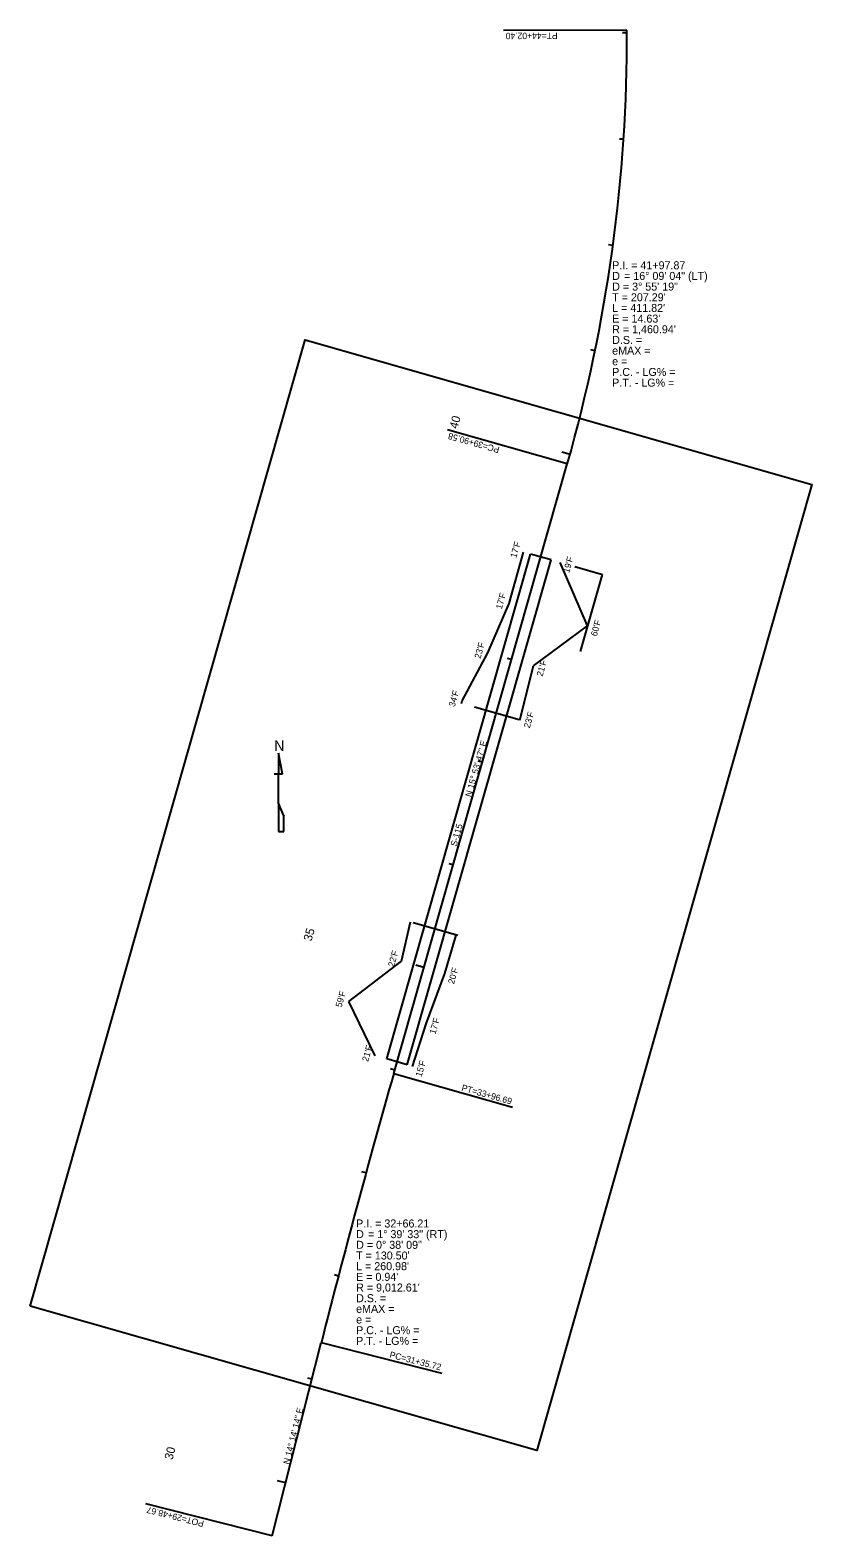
# Model space of a CAD drawing. Extents: x 1619269 to 1623088, y 1189107 to 1192385.
# Drawn here: x 1619269 to 1620002, y 1190974 to 1192385 of the extents above; entities that cross this region are included whole.
import ezdxf

# ---------------------------------------------------------------- set-up
doc = ezdxf.new("R2010")
doc.units = 0
for name, color, linetype in [('GN_Clip', 7, 'Continuous'), ('RD_EX_Misc', 7, 'Continuous'), ('RD_HC_Cl', 7, 'Continuous'), ('RD_HC_Data', 7, 'Continuous'), ('RD_HC_Data_Tic', 7, 'Continuous'), ('RD_HC_TX_Sta50', 7, 'Continuous'), ('RD_PD_Bridge', 7, 'Continuous'), ('RD_PD_CstnLmt', 7, 'Continuous'), ('RD_PD_CstnLmt_TX', 7, 'Continuous'), ('RD_PD_Final_TrvlWay', 7, 'Continuous'), ('RD_PD_RW', 7, 'Continuous'), ('RD_TX_RoadID', 7, 'Continuous')]:
    doc.layers.add(name, color=color, linetype=linetype)

msp = doc.modelspace()

# ---------------------------------------------------------------- linework, layer by layer
at = {"layer": 'GN_Clip'}
msp.add_lwpolyline([(1619269.5, 1191189.2), (1619527.3, 1192094.7), (1620002.2, 1191959.4), (1619744.3, 1191054)], close=True, dxfattribs=at)
at = {"layer": 'RD_EX_Misc'}
for p, q in [((1619506.1, 1191688), (1619502.2, 1191707.6)), ((1619502.2, 1191707.6), (1619502.2, 1191707.6)), ((1619502.2, 1191707.6), (1619502.2, 1191688)), ((1619498.3, 1191688), (1619502.2, 1191688)), ((1619502.2, 1191660.8), (1619502.2, 1191688)), ((1619502.2, 1191688), (1619506.1, 1191688)), ((1619506.1, 1191688), (1619506.1, 1191688.3)), ((1619507.1, 1191648.8), (1619502.2, 1191660.8)), ((1619502.2, 1191660.8), (1619502.2, 1191634.1)), ((1619507.1, 1191634.1), (1619507.1, 1191649)), ((1619507.1, 1191649), (1619507.1, 1191648.8)), ((1619502.2, 1191634.1), (1619507.1, 1191634.1))]:
    msp.add_line(p, q, dxfattribs=at)
at = {"layer": 'RD_HC_Cl'}
for p, q in [((1619610.3, 1191407.3), (1619772.9, 1191978.5)), ((1619496.4, 1190974), (1619542.4, 1191155.3))]:
    msp.add_line(p, q, dxfattribs=at)
for centre, radius, start, end in [((1618367.9, 1192378.6), 1460.9, 344.1036, 0.2547), ((1628278.2, 1188938.7), 9012.6, 164.10357, 165.76267)]:
    msp.add_arc(centre, radius, start, end, dxfattribs=at)
at = {"layer": 'RD_HC_Data'}
for p, q in [((1619828.8, 1192385.1), (1619713.1, 1192384.6)), ((1619772.9, 1191978.5), (1619660.7, 1192010.4)), ((1619610.3, 1191407.3), (1619721.5, 1191375.6)), ((1619542.4, 1191155.3), (1619655.4, 1191126.6)), ((1619496.4, 1190974), (1619377.9, 1191004.1))]:
    msp.add_line(p, q, dxfattribs=at)
at = {"layer": 'RD_HC_Data_Tic'}
for p, q in [((1619828.8, 1192382.7), (1619824.8, 1192382.7)), ((1619825.6, 1192282.8), (1619821.7, 1192283)), ((1619815.7, 1192183.3), (1619811.7, 1192183.8)), ((1619798.9, 1192084.7), (1619795, 1192085.5)), ((1619775.5, 1191987.5), (1619767.8, 1191989.7)), ((1619748.1, 1191891.3), (1619744.3, 1191892.4)), ((1619720.7, 1191795.2), (1619716.9, 1191796.3)), ((1619693.3, 1191699), (1619689.5, 1191700.1)), ((1619665.9, 1191602.8), (1619662.1, 1191603.9)), ((1619638.6, 1191506.6), (1619630.9, 1191508.8)), ((1619611.2, 1191410.5), (1619607.3, 1191411.6)), ((1619584.3, 1191314.1), (1619580.4, 1191315.2)), ((1619558.5, 1191217.5), (1619554.6, 1191218.6)), ((1619533.6, 1191120.7), (1619529.8, 1191121.7)), ((1619509, 1191023.7), (1619501.3, 1191025.7))]:
    msp.add_line(p, q, dxfattribs=at)
at = {"layer": 'RD_PD_Bridge'}
for p, q in [((1619727.9, 1191738.6), (1619686.1, 1191750.5)), ((1619670.4, 1191536.6), (1619628.6, 1191548.5))]:
    msp.add_line(p, q, dxfattribs=at)
at = {"layer": 'RD_PD_CstnLmt'}
for p, q in [((1619718.4, 1191847.8), (1619732, 1191895.9)), ((1619792, 1191826.9), (1619766.1, 1191886.2)), ((1619698.4, 1191801.5), (1619718.4, 1191847.8)), ((1619741.2, 1191789.3), (1619792, 1191826.9)), ((1619674.3, 1191756.4), (1619698.4, 1191801.5)), ((1619729.2, 1191740.8), (1619741.2, 1191789.3)), ((1619673.7, 1191754), (1619674.3, 1191756.4)), ((1619728.5, 1191738.4), (1619729.2, 1191740.8)), ((1619617.4, 1191512.7), (1619625.9, 1191549.3)), ((1619658.2, 1191501), (1619668.9, 1191537)), ((1619568.2, 1191474.7), (1619617.4, 1191512.7)), ((1619640.8, 1191454), (1619658.2, 1191501)), ((1619593, 1191423.9), (1619568.2, 1191474.7)), ((1619627.8, 1191414), (1619640.8, 1191454))]:
    msp.add_line(p, q, dxfattribs=at)
at = {"layer": 'RD_PD_Final_TrvlWay'}
for p, q in [((1619603.7, 1191420.9), (1619738.5, 1191894.1)), ((1619623, 1191415.4), (1619757.7, 1191888.6)), ((1619757.7, 1191888.6), (1619738.5, 1191894.1)), ((1619623, 1191415.4), (1619603.7, 1191420.9))]:
    msp.add_line(p, q, dxfattribs=at)
at = {"layer": 'RD_PD_RW'}
for p in [(1619779.9, 1191882.3), (1619785.3, 1191802.8)]:
    msp.add_line(p, (1619805.8, 1191874.9), dxfattribs=at)

# ---------------------------------------------------------------- texts
at = {"layer": 'RD_EX_Misc'}
msp.add_text('N', height=10, dxfattribs=at).set_placement((1619498.2, 1191709.5))
at = {"layer": 'RD_HC_Data'}
for s, rotation, p in [('PT=44+02.40', 180.2547, (1619763.8, 1192382.8)), ('PC=39+90.58', 164.1036, (1619709.9, 1191994.3)), ('N 15%%d 53\' 47" E', 74.1036, (1619682.9, 1191666)), ('PT=33+96.69', 344.1036, (1619673.3, 1191391.4)), ('PC=31+35.72', 345.7627, (1619605.9, 1191141.2)), ('N 14%%d 14\' 14" E', 75.7627, (1619512.3, 1191040.5)), ('POT=29+48.67', 165.7627, (1619432.9, 1190988))]:
    msp.add_text(s, height=6, rotation=rotation, dxfattribs=at).set_placement(p)
for s, p in [('P.I. = 41+97.87', (1619815, 1192161)), ('D', (1619815, 1192151)), ('    = 16%%d 09\' 04" (LT)', (1619815, 1192151)), ('D = 3%%d 55\' 19"', (1619815, 1192141)), ("T = 207.29'", (1619815, 1192131)), ("L = 411.82'", (1619815, 1192121)), ("E = 14.63'", (1619815, 1192111)), ("R = 1,460.94'", (1619815, 1192101)), ('D.S. = ', (1619815, 1192091)), ('eMAX = ', (1619815, 1192081)), ('e = ', (1619815, 1192071)), ('P.C. - LG% = ', (1619815, 1192061)), ('P.T. - LG% = ', (1619815, 1192051)), ('P.I. = 32+66.21', (1619575, 1191263)), ('D', (1619575, 1191253)), ('    = 1%%d 39\' 33" (RT)', (1619575, 1191253)), ("T = 130.50'", (1619575, 1191233)), ('D = 0%%d 38\' 09"', (1619575, 1191243)), ("L = 260.98'", (1619575, 1191223)), ("E = 0.94'", (1619575, 1191213)), ("R = 9,012.61'", (1619575, 1191203)), ('D.S. = ', (1619575, 1191193)), ('eMAX = ', (1619575, 1191183)), ('e = ', (1619575, 1191173)), ('P.C. - LG% = ', (1619575, 1191163)), ('P.T. - LG% = ', (1619575, 1191153))]:
    msp.add_text(s, height=7.5, dxfattribs=at).set_placement(p)
at = {"layer": 'RD_HC_TX_Sta50'}
for s, rotation, p in [('40', 74.473, (1619669.9, 1192010.9)), ('35', 74.1036, (1619533.1, 1191530.7)), ('30', 75.7627, (1619402.9, 1191044.7))]:
    msp.add_text(s, height=8, rotation=rotation, dxfattribs=at).set_placement(p)
at = {"layer": 'RD_PD_CstnLmt_TX'}
for s, p in [("17'F", (1619725.1, 1191890)), ("19'F", (1619774.6, 1191875.9)), ("17'F", (1619711.5, 1191841.9)), ("60'F", (1619800.5, 1191816.6)), ("23'F", (1619691.5, 1191795.6)), ("21'F", (1619749.7, 1191779)), ("34'F", (1619667.4, 1191750.5)), ("23'F", (1619737.7, 1191730.5)), ("22'F", (1619610.5, 1191506.8)), ("20'F", (1619666.7, 1191490.7)), ("59'F", (1619561.3, 1191468.8)), ("17'F", (1619649.3, 1191443.7)), ("21'F", (1619586.2, 1191418)), ("15'F", (1619636.3, 1191403.7))]:
    msp.add_text(s, height=6, rotation=74.1036, dxfattribs=at).set_placement(p)
at = {"layer": 'RD_TX_RoadID'}
msp.add_text('S-115', height=6, rotation=74.1036, dxfattribs=at).set_placement((1619669.1, 1191619.7))

doc.saveas('drawing.dxf')
